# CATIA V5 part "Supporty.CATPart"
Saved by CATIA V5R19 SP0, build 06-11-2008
Part number: Supporty
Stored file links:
  G:\EU_thinkMotion\CFAO_2010\MMS_groupe3\MMS_groupe3\A reprendre\evulliez\evulliez\Supporty.CATPart

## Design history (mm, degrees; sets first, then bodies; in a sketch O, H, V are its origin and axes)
Body1 (main body)
  Point1: (0, 0, 0)
  Line1: type PtDir, RefPoint Point1, Direction (0, 1, 0), Start -50, End 50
